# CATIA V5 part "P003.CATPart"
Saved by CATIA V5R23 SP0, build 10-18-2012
Part number: P003
Definition: Socle
Bounding box of the stored display mesh (mm): x -28 to 28, y -90 to 400, z -10 to 10
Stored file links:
  C:\wamp\www\COURS\CONCEPTION GMP1\TITRE 02-SEMESTRE 2\03-TP7-PRESSE MECANIQUE\eleve\P003.CATPart
  C:\Documents and Settings\Samuel\Mes documents\Cours\Projet Tutoret\Licence Pro - Presse\Presse\Presse mecanique.CATProduct
  C:\Documents and Settings\Samuel\Mes documents\Cours\Projet Tutoret\Licence Pro - Presse\Presse\Bati gauche.CATPart
  C:\Documents and Settings\Samuel\Mes documents\Cours\Projet Tutoret\Licence Pro - Presse\Presse\bati_droit.CATPart
  C:\wamp\www\COURS\CONCEPTION GMP1\TITRE 02-SEMESTRE 2\03-TP7-PRESSE MECANIQUE\eleve\05-LICP-T02-E-S01.CATProduct
  C:\wamp\www\COURS\CONCEPTION GMP1\TITRE 02-SEMESTRE 2\03-TP7-PRESSE MECANIQUE\eleve\P009.CATPart
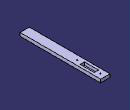
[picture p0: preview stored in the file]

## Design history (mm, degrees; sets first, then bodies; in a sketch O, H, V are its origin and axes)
Set1
  DatumCurve1: linked copy from another document
Body1 (main body)
  Sketch1 on zx-plane, origin (0, 0, 0), H (-1, 0, 0), V (0, 0, 1)
    line L1 (-28, 10) -> (28, 10)
    line L2 (28, 10) -> (28, -10)
    line L3 (28, -10) -> (-28, -10)
    line L4 (-28, -10) -> (-28, 10)
    length L2 = 20
    distance L2 L4 = 56
    horizontal: L1 H, L3 H
    vertical: L2 V, L4 V
    symmetry: L2 L4 V, L1 L3 H
  Pad1: profile Sketch1, direction (0, 1, 0), length 400, opposite side length 90
  Sketch2 on face of Pad1, origin (-4.289, 360.4537, 10), H (1, 0, 0), V (0, 1, 0)
    point P1 (4.289, 9.5463)
    reference projected line E1 (-23.711, 39.5463) -> (32.289, 39.5463) from edge [face of Pad1 | face of Pad1]
    reference projected line E2 (-23.711, -450.4537) -> (-23.711, 39.5463) from edge [face of Pad1 | face of Pad1]
    distance P1 E1 = 30
    distance P1 E2 = 28
  Hole1: placed by Sketch2, at (0, 370, 10) direction (0, 0, -1), diameter 6, through (limit type 3)
  Sketch3 on yz-plane, origin (0, 0, 0), H (0, 1, 0), V (0, 0, 1)
    line L1 (346, 17) -> (261, 17)
    line L2 (261, 17) -> (261, -8)
    line L3 (261, -8) -> (346, -8)
    line L4 (346, -8) -> (346, 17)
    reference projected line E1 (400, 10) -> (400, -10) from edge [face of Pad1 | face of Pad1]
    reference projected line E2 (-90, 10) -> (400, 10) from edge [face of Pad1 | face of Pad1]
    distance L4 E1 = 54
    distance L3 E2 = 18
    distance L4 L2 = 85
    distance L1 L3 = 25
    horizontal: L1 H, L3 H
    vertical: L2 V, L4 V
  Pocket1: profile Sketch3, direction (-1, 0, 0), length 13, mirrored extent
  Sketch4 on face of Pad1, origin (-16.9842, 230.1926, 10), H (1, 0, 0), V (0, 1, 0)
    point P1 (16.9842, -1.1926)
    reference intersected line E1 through (16.9842, 0) direction (0, 1) from yz-plane
    reference projected point E2 (16.9842, -1.1926) from edge of DatumCurve1
    coincidence: P1 E1, P1 E2
  Hole2: placed by Sketch4, at (0, 229, 10) direction (0, 0, -1), diameter 6.647, through (limit type 3), threaded "M8", thread diameter 8, thread depth 10, pitch 1.25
